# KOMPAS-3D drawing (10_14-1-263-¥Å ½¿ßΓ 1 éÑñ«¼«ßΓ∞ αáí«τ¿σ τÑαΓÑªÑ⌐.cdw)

Views: Вид 1, Вид 2
Referenced files in C:\Program Files\ASCON\KOMPAS-3D V10\Sys\: Graphic.lcs
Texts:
  Стена
  Металлич. перекрытия
  Сэндвич-панели 100
  Блоки фундаментные 400
  Сэндвич-панели 150
  Текст на чертеже
  Размерные надписи
  Шероховатость
  Линия-выноска #1
  Линия-выноска #2
  Линия-выноска #3
  Отклонения формы и база
  Заголовок таблицы
  Ячейка таблицы
  Стрелка вида
  Обозначение изменения
  Фигурная скобка
  Номер узла
  Марка координационной оси
  VRCB
  Выносная надпись
  Обозначение узла
  Марка/позиционное обозначение с линией-выноской
  Марка/позиционное обозначение на линии
  Марка/позиционное обозначение без линии-выноски
  Normal
  txt
  Body Text
  heading 1
  Знак Знак Знак Знак Знак Знак
  Verdana
  Лит-Масса-Масштаб
  Материал-Предприятие
  MS Sans Serif
  Simplex
  Txt
  Title Specification
  Body Specification ( left align )
  Body Specificaton ( centered )
  Без имени
  Additional DXF text style 0
  Обычный
  Термин
  Список определений
  Адрес
  Цитаты
  Форматированный
  Courier New
  Z-конец формы
  Z-начало формы
  ТекстШаг1
  Денис
  heading 2
  AGOpus
  footer
  Title
  ООббыыччнныыйй
  Definition Term
  Definition List
  Address
  Blockquote
  Preformatted
  z-Bottom of Form
  z-Top of Form
  TXT
  header
  heading 8
  heading 3
  heading 6
  heading 7
  russ
  ТТееррммиинн
  ССппииссоокк ооппррееддееллеенниийй
  ААддрреесс
  ЦЦииттааттыы
  ФФооррммааттиирроовваанннныыйй
  Z-ккооннеецц ффооррммыы
  Z-ннааччааллоо ффооррммыы
  Абзац Знак
  heading 4
  heading 5
  heading 9
  GOST 2.304 type A
  rustxt
  цепи
  ссылки
  Маркировка
  Подпись в квадратике
  табл
  ЗОНА_привяз
  маркировка
  ГОСТ_МНЕ
  ESK - Обозначение
  текст переноса
  Тексты. 3,2
  Body Text 3
  клеммы, контакты
  тексты табл
  ISOCP
  HeliosLight
  Pa3
  Pa1
  Шрифт 2.5
  Заголовки
  RUSTXT
  NormalParagraphStyle
  Три с половиной
  style2
  надписи
  экспликация
  Здание
  Оси
  Лист
  Ведомость рабочих чертежей комплекта 263-ЭП
  Опросный лист на изготовление реакторных модульного типа
  Расположение оборудования в реакторной 1Т. План. Виды
  Расположение оборудования в реакторной 2Т. План. Виды
  План и схема силовой и осветительной сети в реакторной 1Т
  План и схема силовой и осветительной сети в реакторной 2Т
  Монтажная схема силового щита реакторной 1Т,2Т
  Схема обогрева шкафов собственных нужд реакторных
  Ведомость ссылочных и прилагаемых документов
  Прилагаемые документы
  Фундамент под здание реакторной
  POLYLINE_STYLE_0.73_RGB_0_0_0
  DIVIDE_RGB_0_0_0_SC_1_THICK_0.18
  DASHDOT1_RGB_0_0_0_SC_1_THICK_0.18
  осн 2
  K5LT_BASIC_RGB_0_0_255_THICK_0.3
  K5LT_AXLED_RGB_255_255_0_SC_1_THICK_0.09
  K5LT_REINFORCED_RGB_255_0_0_THICK_0.6
  POLYLINE_STYLE_0.30_RGB_0_0_255
  K5LT_THIN_RGB_0_0_0_THICK_0.09
  K5LT_THIN_INCLUDED_TO_HATCHING_RGB_0_0_0_THICK_0.09
  K5LT32769_RGB_0_0_0_THICK_0.09
  K5LT_THIN_RGB_0_0_0_THICK_0.13
  Стили документа
  Бетон
  Бетон 0
  Бетон 1
  Бетон 2
  Бетон 3
  Ведомость рабочих чертежей
  комплекта 263-ЭП
  Реконструкция ПС 110 кВ Опорная
  (замена трансформаторов 16МВА на 40МВА)
  Разраб.
  Скахин
  Ведомость эскизного проекта
  ГИП
  Маленкин
Dimensions and other numbers on the sheet: 10/14-1-263-ЭП; 5; 0; 7; 2,5; 3.5; 2.5; 1,8; 2,5 (контакты, клеммы); 2.5 курсив; 2,5_3; 3,2 (надписи); 3,5_01; 2,5_01; 3,5_tabl; 5_заголовок; 2,3_; 3,2_; 3,2_зона не привяз; 2,5 грязносинь; 5,0_белый_подчёркнутый; 3,2; 3.2 фиол; 3,5; 3,2 элементы; 3,2 линия; 3,2 таблица; 3.2 маркировка; 2.5_Э5_надписи; 2.5_Э5_ссылки; 2.5_кабель; 3.2; 2.5 надписи; 3,2 (Зоны); 3 и 5; 1; 2; 3; 4; 6; 8; 10/14-1-113-КС лист 11; 77; 0193.0-06-ИОС7.1-; 11.12; 9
